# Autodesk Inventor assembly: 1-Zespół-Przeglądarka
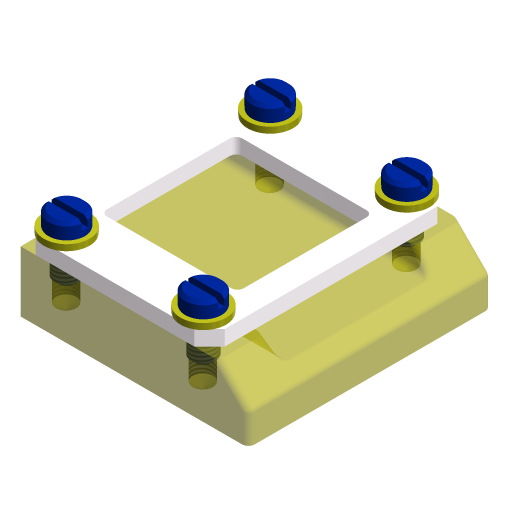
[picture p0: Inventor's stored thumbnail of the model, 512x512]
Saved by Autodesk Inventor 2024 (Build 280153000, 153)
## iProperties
Created: 2023-03
Part Number: 1-Zespół-Przeglądarka
Document SubType Name: Assembly
Designer: Andrzej Jaskulski
Checked By: A.J.
Engr Approved By: Andrzej Jaskulski
Mfg Approved By: Andrzej Jaskulski
Authority: A.J.
Company: ATC
Control State: 0
Master: False
Checked Out: False
Shininess: 20.0
Length Units: 11269
Angle Units: 11279
Time Units: 11290
Mass Units: 11283
Length Display Precision: 3
Angle Display Precision: 2
Density: 0.0
Volumn: 0.0
Area: 0.0
PropertySet Name: Model Information
Title: A.J.: Kurs R2024-MEP
Author: Andrzej Jaskulski
Revision Number: 1/24
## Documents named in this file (5)
- C:\Users\AndJas\Documents\R2024-MEP\Obszar roboczy\1-Zespół-Przeglądarka.iam
- C:\Users\AndJas\Documents\R2024-MEP\Obszar roboczy\PG-ZP.ipt
- C:\Users\AndJas\Documents\R2024-MEP\Obszar roboczy\Płyta-ZP.ipt
- C:\Users\AndJas\Documents\R2024-MEP\Obszar roboczy\POD-ZP.ipt
- C:\Users\AndJas\Documents\R2024-MEP\Obszar roboczy\Wkręt-ZP.ipt
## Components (10 placed, 4 different names)
1. Płyta-ZP:1 — Zestawiające:1, Zestawiające:2
2. PG-ZP:1 — Zestawiające:1, Zestawiające:2, Wstawiające:1, Wstawiające:2, Wstawiające:3, Wstawiające:4
3. POD-ZP:1 — Wstawiające:1, Wstawiające:7
4. Wkręt-ZP:1 — Wstawiające:7
5. POD-ZP:2 — Wstawiające:2, Wstawiające:8
6. Wkręt-ZP:2 — Wstawiające:8
7. POD-ZP:3 — Wstawiające:3, Wstawiające:5
8. Wkręt-ZP:3 — Wstawiające:5
9. POD-ZP:4 — Wstawiające:4, Wstawiające:6
10. Wkręt-ZP:4 — Wstawiające:6
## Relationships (10: Insert 8, Mate 2)
- Zestawiające:1 [Mate]: Płyta-ZP:1 ↔ PG-ZP:1
- Zestawiające:2 [Mate]: Płyta-ZP:1 ↔ PG-ZP:1
- Wstawiające:1 [Insert]: PG-ZP:1 ↔ POD-ZP:1
- Wstawiające:2 [Insert]: PG-ZP:1 ↔ POD-ZP:2
- Wstawiające:3 [Insert]: PG-ZP:1 ↔ POD-ZP:3
- Wstawiające:4 [Insert]: PG-ZP:1 ↔ POD-ZP:4
- Wstawiające:5 [Insert]: POD-ZP:3 ↔ Wkręt-ZP:3
- Wstawiające:6 [Insert]: POD-ZP:4 ↔ Wkręt-ZP:4
- Wstawiające:7 [Insert]: POD-ZP:1 ↔ Wkręt-ZP:1
- Wstawiające:8 [Insert]: POD-ZP:2 ↔ Wkręt-ZP:2
